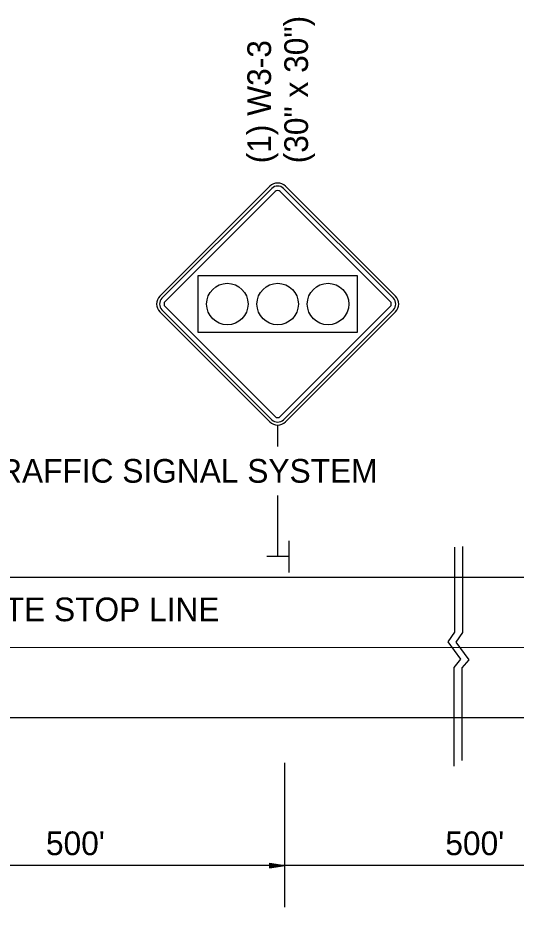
# Model space of a CAD drawing. Extents: x 1930579 to 1939784, y 596179 to 597522.
# Drawn here: x 1937559.9 to 1937686.1, y 596418.8 to 596644.1 of the extents above; entities that cross this region are included whole.
import ezdxf

# ---------------------------------------------------------------- set-up
doc = ezdxf.new("R2010")
doc.units = 0
for name, color, linetype in [('Default', 7, 'Continuous'), ('P_TC_Signs_Permanent', 7, 'Continuous'), ('R_Annotation', 7, 'Continuous')]:
    doc.layers.add(name, color=color, linetype=linetype)

msp = doc.modelspace()

# ---------------------------------------------------------------- linework, layer by layer
at = {"layer": 'Default'}
for p, q in [((1937628.52, 596511.65), (1937628.52, 596503.64)), ((1937628.4, 596507.67), (1937622.94, 596507.67)), ((1937444.6, 596502.47), (1938059.31, 596502.42)), ((1937443.89, 596484.68), (1938161.51, 596484.63)), ((1937444.38, 596466.89), (1937598.49, 596466.89)), ((1937444.38, 596466.89), (1938059.31, 596466.85)), ((1937627.45, 596418.83), (1937627.45, 596455.43)), ((1937627.45, 596429.42), (1937526.32, 596429.42)), ((1937623.61, 596429.99), (1937627.45, 596429.42)), ((1937623.61, 596429.99), (1937623.61, 596428.84)), ((1937623.61, 596429.9), (1937626.81, 596429.42)), ((1937623.61, 596429.8), (1937626.15, 596429.42)), ((1937623.61, 596429.7), (1937625.51, 596429.42)), ((1937623.61, 596429.6), (1937624.86, 596429.42)), ((1937623.61, 596429.51), (1937624.22, 596429.42)), ((1937623.61, 596428.84), (1937627.45, 596429.42)), ((1937623.61, 596429.23), (1937624.86, 596429.42)), ((1937623.61, 596429.04), (1937626.15, 596429.42)), ((1937623.61, 596428.94), (1937626.81, 596429.42)), ((1937623.61, 596429.13), (1937625.51, 596429.42)), ((1937623.61, 596429.33), (1937624.22, 596429.42)), ((1937726.35, 596429.42), (1937626.6, 596429.42))]:
    msp.add_line(p, q, dxfattribs=at)
for points in [[(1937672.47, 596510.25), (1937672.47, 596488.44), (1937670.8, 596485.97), (1937674.04, 596481.54), (1937672.34, 596479.5), (1937672.33, 596456)], [(1937670.42, 596510.05), (1937670.42, 596488.53), (1937668.76, 596486.06), (1937672, 596481.63), (1937670.29, 596479.58), (1937670.29, 596454.56)]]:
    msp.add_lwpolyline(points, dxfattribs=at)
at = {"layer": 'P_TC_Signs_Permanent'}
for p, q in [((1937595.84, 596573.62), (1937623.68, 596601.46)), ((1937596.37, 596573.09), (1937624.21, 596600.93)), ((1937627.13, 596600.93), (1937654.97, 596573.09)), ((1937627.66, 596601.46), (1937655.5, 596573.62)), ((1937625.01, 596600.13), (1937597.16, 596572.29)), ((1937654.17, 596572.29), (1937626.33, 596600.13)), ((1937597.16, 596570.97), (1937625.01, 596543.12)), ((1937626.33, 596543.12), (1937654.17, 596570.97)), ((1937623.68, 596541.8), (1937595.84, 596569.64)), ((1937624.21, 596542.33), (1937596.37, 596570.17)), ((1937654.97, 596570.17), (1937627.13, 596542.33)), ((1937655.5, 596569.64), (1937627.66, 596541.8))]:
    msp.add_line(p, q, dxfattribs=at)
msp.add_lwpolyline([(1937645.92, 596564.5), (1937645.92, 596578.75), (1937605.42, 596578.75), (1937605.42, 596564.5)], close=True, dxfattribs=at)
for centre in [(1937612.92, 596571.63), (1937625.67, 596571.63), (1937638.42, 596571.63)]:
    msp.add_circle(centre, 5.25, dxfattribs=at)
for centre, radius, start, end in [((1937625.67, 596599.47), 2.81, 45, 135), ((1937625.67, 596599.47), 2.06, 45, 135), ((1937625.67, 596599.47), 0.938, 45, 135), ((1937597.83, 596571.63), 2.81, 135, 225), ((1937653.51, 596571.63), 2.81, 315, 45), ((1937597.83, 596571.63), 2.06, 135, 225), ((1937597.83, 596571.63), 0.938, 135, 225), ((1937653.51, 596571.63), 0.938, 315, 45), ((1937653.51, 596571.63), 2.06, 315, 45), ((1937625.67, 596543.79), 2.81, 225, 315), ((1937625.67, 596543.79), 2.06, 225, 315), ((1937625.67, 596543.79), 0.938, 225, 315)]:
    msp.add_arc(centre, radius, start, end, dxfattribs=at)
at = {"layer": 'R_Annotation'}
for p, q in [((1937625.67, 596535.56), (1937625.67, 596540.97)), ((1937625.67, 596507.67), (1937625.67, 596523.13))]:
    msp.add_line(p, q, dxfattribs=at)

# ---------------------------------------------------------------- texts
at = {"layer": 'Default'}
for s, height, p in [('PORTABLE TRAFFIC SIGNAL SYSTEM', 5.9996, (1937505.19, 596526.37)), ('12" WHITE STOP LINE', 5.9996, (1937526.95, 596491.28)), ("500'", 6, (1937566.99, 596432.02)), ("500'", 6, (1937668.12, 596432.02))]:
    msp.add_text(s, height=height, rotation=360, dxfattribs=at).set_placement(p)
at = {"layer": 'R_Annotation'}
for s, height, p in [('(30" x 30")', 5.9996, (1937633.35, 596607.28)), ('(1) W3-3', 6, (1937623.99, 596607.28))]:
    msp.add_text(s, height=height, rotation=90, dxfattribs=at).set_placement(p)

doc.saveas('drawing.dxf')
